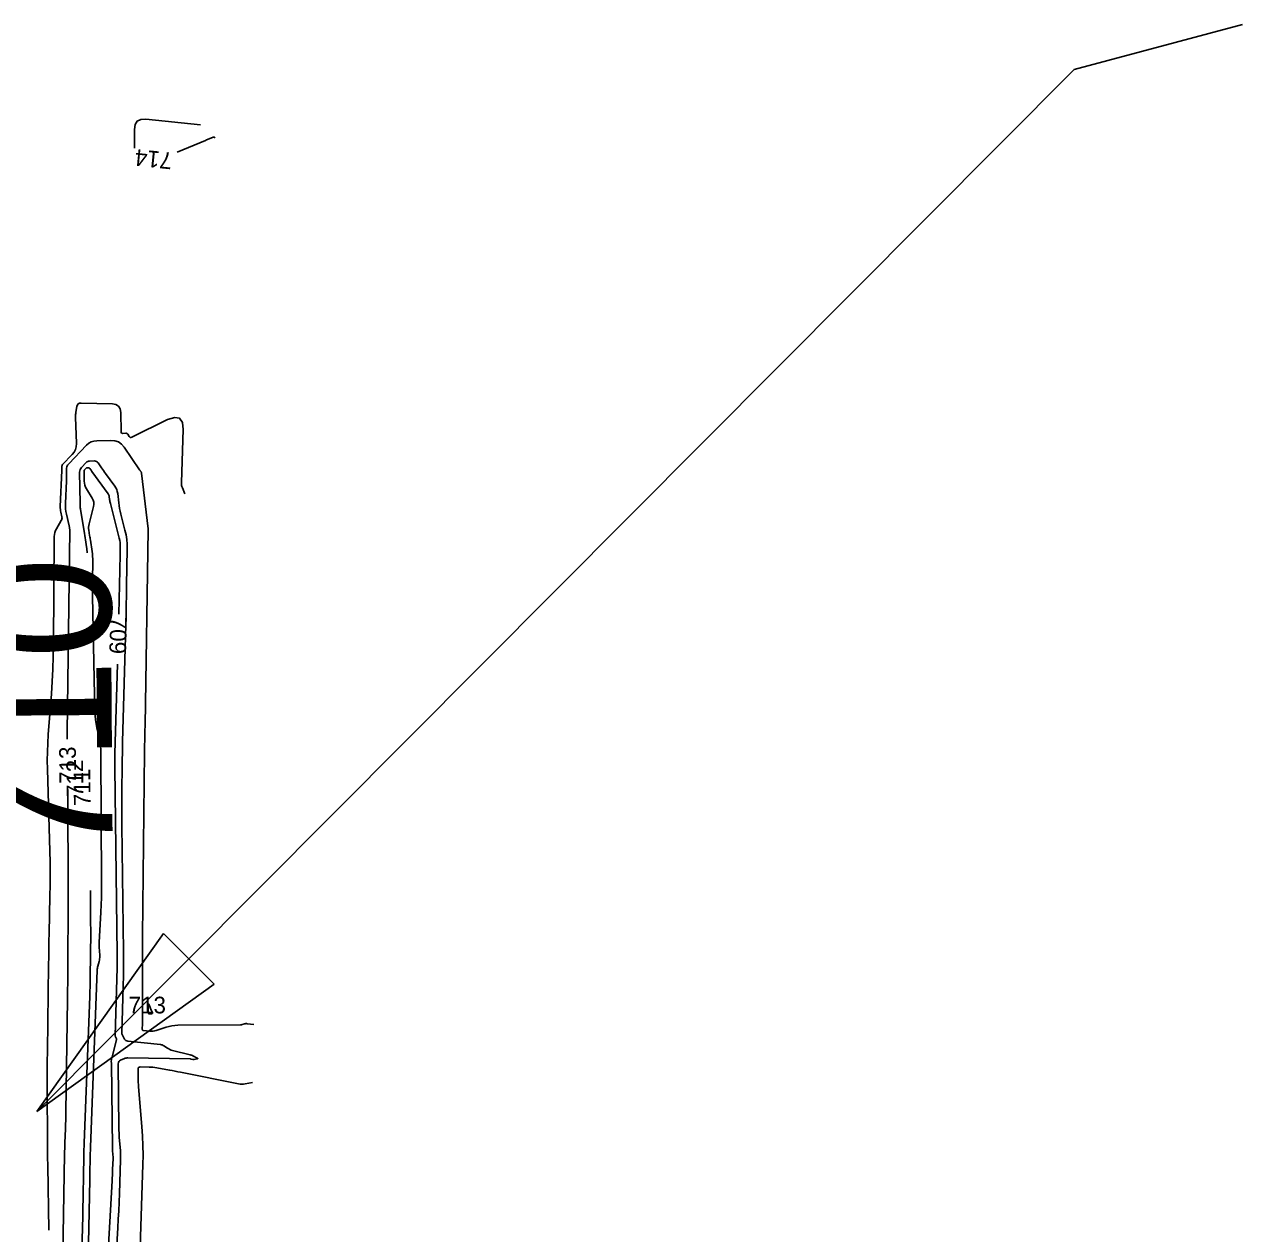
# Model space of a CAD drawing. Extents: x -361782338 to 28259792, y -263199453 to 8342113.
# Drawn here: x 1403882.9 to 1404174.4, y 578304.2 to 578593.6 of the extents above; entities that cross this region are included whole.
import ezdxf

# ---------------------------------------------------------------- set-up
doc = ezdxf.new("R2010")
doc.units = 0
for name, color, linetype in [('DT_X_Contour_Minor', 7, 'Continuous'), ('Level 19', 7, 'Continuous'), ('Level 40', 7, 'Continuous')]:
    doc.layers.add(name, color=color, linetype=linetype)

msp = doc.modelspace()

# ---------------------------------------------------------------- linework, layer by layer
at = {"layer": 'DT_X_Contour_Minor'}
for points in [[(1403925.03, 578569.52), (1403911.93, 578570.88), (1403910.74, 578570.83), (1403909.88, 578570.4), (1403909.37, 578569.6), (1403909.2, 578568.41), (1403909.21, 578563.97)], [(1403919.42, 578562.96), (1403926.19, 578565.8), (1403926.42, 578565.9), (1403926.65, 578565.99), (1403926.88, 578566.09), (1403927.1, 578566.19), (1403928.04, 578566.58), (1403928.11, 578566.6), (1403928.17, 578566.61), (1403928.22, 578566.6), (1403928.28, 578566.57), (1403928.55, 578566.42)], [(1403921.28, 578481.19), (1403920.68, 578482.62), (1403920.57, 578482.93), (1403920.49, 578483.24), (1403920.45, 578483.57), (1403920.44, 578483.89), (1403920.86, 578496.57), (1403920.68, 578498.32), (1403920, 578499.31), (1403918.83, 578499.52), (1403917.15, 578498.97), (1403908.55, 578494.77), (1403908.37, 578494.71), (1403908.21, 578494.72), (1403908.07, 578494.79), (1403907.95, 578494.93), (1403907.58, 578495.48), (1403907.49, 578495.59), (1403907.38, 578495.66), (1403907.26, 578495.7), (1403907.13, 578495.71), (1403906.34, 578495.69), (1403906.19, 578495.71), (1403906.09, 578495.77), (1403906.02, 578495.87), (1403906, 578496.02), (1403905.93, 578500.67), (1403905.79, 578501.55), (1403905.41, 578502.18), (1403904.78, 578502.57), (1403903.91, 578502.72), (1403896.42, 578502.94), (1403896.04, 578502.89), (1403895.74, 578502.74), (1403895.54, 578502.49), (1403895.42, 578502.12), (1403895.18, 578500.75), (1403895.14, 578500.46), (1403895.11, 578500.16), (1403895.1, 578499.87), (1403895.1, 578499.57), (1403895.32, 578493.25), (1403895.28, 578492.5), (1403895.09, 578491.81), (1403894.77, 578491.18), (1403894.31, 578490.59), (1403892.02, 578488.21), (1403891.94, 578488.1), (1403891.87, 578487.98), (1403891.84, 578487.85), (1403891.83, 578487.7), (1403891.84, 578487.23), (1403891.84, 578487.12), (1403891.84, 578487.02), (1403891.84, 578486.92), (1403891.83, 578486.82), (1403891.46, 578478.17), (1403891.46, 578477.83), (1403891.48, 578477.49), (1403891.52, 578477.15), (1403891.59, 578476.81), (1403891.84, 578475.72), (1403891.87, 578475.49), (1403891.86, 578475.27), (1403891.8, 578475.05), (1403891.7, 578474.84), (1403890.52, 578472.86), (1403890.29, 578472.43), (1403890.13, 578471.98), (1403890.04, 578471.52), (1403890, 578471.03), (1403889.83, 578445.24), (1403889.78, 578442.27), (1403889.68, 578439.29), (1403889.53, 578436.32), (1403889.33, 578433.35), (1403888.58, 578423.65), (1403888.44, 578421.58), (1403888.37, 578419.5), (1403888.34, 578417.41), (1403888.38, 578415.33), (1403888.95, 578395.73), (1403889.01, 578393.03), (1403889.03, 578390.32), (1403889.03, 578387.62), (1403888.98, 578384.92), (1403888.79, 578376.09), (1403888.75, 578374.19), (1403888.72, 578372.3), (1403888.68, 578370.41), (1403888.66, 578368.52), (1403888.36, 578347.94), (1403888.32, 578345.21), (1403888.3, 578342.48), (1403888.3, 578339.75), (1403888.31, 578337.01), (1403888.36, 578328.09), (1403888.37, 578326.17), (1403888.39, 578324.26), (1403888.42, 578322.35), (1403888.44, 578320.44)], [(1403937.79, 578354.22), (1403936.15, 578354.41), (1403935.99, 578354.43), (1403935.83, 578354.42), (1403935.67, 578354.4), (1403935.51, 578354.35), (1403935, 578354.19), (1403934.89, 578354.16), (1403934.78, 578354.14), (1403934.67, 578354.12), (1403934.55, 578354.12), (1403919.58, 578354.02), (1403918.88, 578353.99), (1403918.18, 578353.9), (1403917.49, 578353.77), (1403916.81, 578353.58), (1403914.37, 578352.79), (1403914.01, 578352.69), (1403913.65, 578352.63), (1403913.29, 578352.62), (1403912.92, 578352.63), (1403911.27, 578352.8), (1403911.23, 578352.81), (1403911.2, 578352.83), (1403911.17, 578352.85), (1403911.15, 578352.88), (1403911.09, 578352.99), (1403911.08, 578353.01), (1403911.07, 578353.04), (1403911.07, 578353.06), (1403911.06, 578353.09), (1403911.1, 578354.4), (1403911.11, 578354.68), (1403911.11, 578354.96), (1403911.11, 578355.24), (1403911.12, 578355.53), (1403911.15, 578368.69), (1403911.15, 578369.36), (1403911.15, 578370.02), (1403911.15, 578370.69), (1403911.14, 578371.35), (1403911.11, 578373.53), (1403911.11, 578373.99), (1403911.11, 578374.46), (1403911.11, 578374.93), (1403911.11, 578375.39), (1403911.6, 578419.37), (1403911.61, 578420.01), (1403911.62, 578420.65), (1403911.63, 578421.29), (1403911.65, 578421.93), (1403911.7, 578424.02), (1403911.71, 578424.47), (1403911.72, 578424.92), (1403911.73, 578425.37), (1403911.74, 578425.82), (1403912.51, 578472.56), (1403912.51, 578472.58), (1403912.51, 578472.61), (1403912.51, 578472.63), (1403912.5, 578472.66), (1403912.48, 578472.74), (1403912.48, 578472.76), (1403912.47, 578472.77), (1403912.47, 578472.79), (1403912.47, 578472.81), (1403910.91, 578486.13), (1403910.89, 578486.23), (1403910.86, 578486.32), (1403910.82, 578486.41), (1403910.77, 578486.49), (1403910.58, 578486.75), (1403910.54, 578486.8), (1403910.5, 578486.86), (1403910.46, 578486.91), (1403910.42, 578486.97), (1403906.77, 578492.36), (1403906.13, 578493.1), (1403905.39, 578493.63), (1403904.52, 578493.93), (1403903.55, 578494.01), (1403900.18, 578493.92), (1403899.49, 578493.84), (1403898.85, 578493.63), (1403898.27, 578493.3), (1403897.74, 578492.84), (1403893.47, 578488.38), (1403893.21, 578488.05), (1403893.03, 578487.7), (1403892.93, 578487.32), (1403892.9, 578486.92), (1403892.93, 578485.53), (1403892.93, 578485.23), (1403892.93, 578484.94), (1403892.92, 578484.64), (1403892.91, 578484.34), (1403892.68, 578478.91), (1403892.68, 578478.26), (1403892.71, 578477.61), (1403892.8, 578476.97), (1403892.92, 578476.33)], [(1403922.81, 578345.95), (1403923.19, 578345.87), (1403923.27, 578345.86), (1403923.35, 578345.86), (1403923.43, 578345.86), (1403923.51, 578345.87), (1403924.22, 578346), (1403924.33, 578346.03), (1403924.37, 578346.07), (1403924.35, 578346.13), (1403924.25, 578346.19), (1403923.34, 578346.66), (1403923.14, 578346.75), (1403922.94, 578346.84), (1403922.74, 578346.91), (1403922.53, 578346.97), (1403918.31, 578348.02), (1403918, 578348.11), (1403917.7, 578348.23), (1403917.41, 578348.37), (1403917.14, 578348.54), (1403916.25, 578349.12), (1403916.06, 578349.23), (1403915.85, 578349.32), (1403915.64, 578349.38), (1403915.42, 578349.41), (1403907.6, 578350.21), (1403907.36, 578350.27), (1403907.14, 578350.37), (1403906.96, 578350.52), (1403906.82, 578350.73), (1403906.39, 578351.48), (1403906.31, 578351.64), (1403906.25, 578351.81), (1403906.22, 578351.99), (1403906.22, 578352.17), (1403906.52, 578363.42), (1403906.54, 578364.23), (1403906.55, 578365.04), (1403906.56, 578365.85), (1403906.57, 578366.66), (1403906.58, 578369.31), (1403906.58, 578369.88), (1403906.57, 578370.44), (1403906.57, 578371.01), (1403906.56, 578371.58), (1403906.2, 578401.89), (1403906.18, 578403.88), (1403906.18, 578405.86), (1403906.18, 578407.85), (1403906.2, 578409.83), (1403906.27, 578416.32), (1403906.29, 578417.71), (1403906.31, 578419.1), (1403906.34, 578420.49), (1403906.37, 578421.88), (1403907.12, 578449.87), (1403907.18, 578452.23), (1403907.23, 578454.58), (1403907.28, 578456.94), (1403907.32, 578459.3), (1403907.46, 578468.03), (1403907.45, 578469.17), (1403907.35, 578470.3), (1403907.18, 578471.42), (1403906.94, 578472.53), (1403905.96, 578476.36), (1403905.8, 578477.04), (1403905.66, 578477.71), (1403905.54, 578478.4), (1403905.45, 578479.08), (1403905.19, 578481.33), (1403905.1, 578481.8), (1403904.96, 578482.25), (1403904.76, 578482.67), (1403904.5, 578483.07), (1403902.29, 578486.08), (1403902.04, 578486.43), (1403901.79, 578486.77), (1403901.55, 578487.12), (1403901.31, 578487.47), (1403900.53, 578488.62), (1403900.35, 578488.83), (1403900.14, 578488.98), (1403899.89, 578489.07), (1403899.61, 578489.1), (1403898.46, 578489.06), (1403898.22, 578489.04), (1403898.01, 578488.96), (1403897.81, 578488.85), (1403897.63, 578488.69), (1403896.53, 578487.55), (1403896.33, 578487.3), (1403896.19, 578487.02), (1403896.1, 578486.71), (1403896.08, 578486.38), (1403896.23, 578478.9), (1403896.23, 578478.79), (1403896.23, 578478.68), (1403896.23, 578478.58), (1403896.22, 578478.47)], [(1403905.43, 578452.44), (1403905.71, 578462.95), (1403905.73, 578463.71), (1403905.74, 578464.47), (1403905.76, 578465.23), (1403905.77, 578466), (1403905.81, 578468.48), (1403905.8, 578469.02), (1403905.76, 578469.54), (1403905.68, 578470.07), (1403905.57, 578470.58), (1403903.45, 578478.88), (1403903.39, 578479.12), (1403903.34, 578479.35), (1403903.3, 578479.59), (1403903.27, 578479.83), (1403903.18, 578480.61), (1403903.15, 578480.77), (1403903.1, 578480.93), (1403903.03, 578481.08), (1403902.94, 578481.22), (1403899.04, 578486.53), (1403898.96, 578486.63), (1403898.89, 578486.74), (1403898.81, 578486.85), (1403898.74, 578486.95), (1403898.5, 578487.31), (1403898.44, 578487.37), (1403898.38, 578487.42), (1403898.3, 578487.45), (1403898.22, 578487.45), (1403897.86, 578487.44), (1403897.79, 578487.44), (1403897.72, 578487.41), (1403897.66, 578487.38), (1403897.61, 578487.33), (1403897.27, 578486.98), (1403897.21, 578486.9), (1403897.16, 578486.81), (1403897.14, 578486.72), (1403897.13, 578486.62), (1403897.18, 578484.27), (1403897.22, 578483.77), (1403897.32, 578483.3), (1403897.49, 578482.84), (1403897.73, 578482.4), (1403899.09, 578480.19), (1403899.32, 578479.71), (1403899.45, 578479.21), (1403899.48, 578478.7), (1403899.39, 578478.17), (1403898.33, 578474.03), (1403898.26, 578473.65), (1403898.22, 578473.26), (1403898.22, 578472.88), (1403898.27, 578472.49), (1403898.48, 578471.23), (1403898.52, 578470.95), (1403898.57, 578470.68), (1403898.61, 578470.41), (1403898.65, 578470.14), (1403899.07, 578467.41), (1403899.14, 578466.82), (1403899.2, 578466.24), (1403899.23, 578465.65), (1403899.23, 578465.06), (1403899.17, 578460.57), (1403899.16, 578459.61), (1403899.16, 578458.65), (1403899.17, 578457.68), (1403899.19, 578456.72), (1403899.75, 578429.02), (1403899.79, 578428.05), (1403899.88, 578427.09), (1403900.02, 578426.14), (1403900.21, 578425.19), (1403900.89, 578422.1), (1403901.01, 578421.43), (1403901.11, 578420.76), (1403901.16, 578420.09), (1403901.19, 578419.41), (1403901.34, 578388.07), (1403901.33, 578386.32), (1403901.3, 578384.57), (1403901.25, 578382.82), (1403901.17, 578381.07), (1403900.79, 578373.81), (1403900.77, 578373.36), (1403900.76, 578372.91), (1403900.77, 578372.46), (1403900.8, 578372.01), (1403900.89, 578370.53), (1403900.89, 578370.22), (1403900.87, 578369.91), (1403900.83, 578369.6), (1403900.75, 578369.29), (1403900.44, 578368.18), (1403900.38, 578367.94), (1403900.33, 578367.69), (1403900.3, 578367.45), (1403900.29, 578367.2)], [(1403892.92, 578476.33), (1403893.57, 578473.53), (1403893.59, 578473.45), (1403893.6, 578473.37), (1403893.62, 578473.29), (1403893.63, 578473.21), (1403893.68, 578472.92), (1403893.69, 578472.88), (1403893.69, 578472.83), (1403893.7, 578472.79), (1403893.71, 578472.75), (1403893.73, 578472.61), (1403893.73, 578472.58), (1403893.73, 578472.54), (1403893.74, 578472.51), (1403893.74, 578472.48), (1403893.11, 578424.21), (1403893.11, 578423.74), (1403893.11, 578423.26), (1403893.11, 578422.78), (1403893.12, 578422.49)], [(1403896.22, 578478.47), (1403896.21, 578478.09), (1403896.21, 578478.03), (1403896.21, 578477.97), (1403896.22, 578477.9), (1403896.23, 578477.84), (1403896.28, 578477.64), (1403896.29, 578477.59), (1403896.3, 578477.55), (1403896.3, 578477.51), (1403896.31, 578477.46), (1403897.18, 578472.24), (1403897.26, 578471.73), (1403897.35, 578471.22), (1403897.43, 578470.71), (1403897.51, 578470.2), (1403897.76, 578468.53), (1403897.81, 578468.17), (1403897.84, 578467.81), (1403897.86, 578467.45), (1403897.86, 578467.09)], [(1403901.44, 578274.79), (1403903.86, 578316.79), (1403903.9, 578317.47), (1403903.93, 578318.14), (1403903.96, 578318.82), (1403903.98, 578319.5), (1403904.07, 578322.16), (1403904.07, 578322.41), (1403904.07, 578322.66), (1403904.06, 578322.91), (1403904.04, 578323.16), (1403903.97, 578323.97), (1403903.96, 578324.15), (1403903.95, 578324.32), (1403903.95, 578324.5), (1403903.94, 578324.67), (1403903.74, 578345.02), (1403903.73, 578345.05), (1403903.73, 578345.08), (1403903.71, 578345.1), (1403903.7, 578345.12), (1403903.64, 578345.19), (1403903.63, 578345.2), (1403903.62, 578345.22), (1403903.62, 578345.23), (1403903.62, 578345.25), (1403903.72, 578345.92), (1403903.74, 578346.06), (1403903.77, 578346.2), (1403903.8, 578346.34), (1403903.84, 578346.48), (1403904.9, 578350.51), (1403904.92, 578350.62), (1403904.92, 578350.72), (1403904.89, 578350.83), (1403904.85, 578350.93), (1403904.67, 578351.25), (1403904.63, 578351.32), (1403904.61, 578351.4), (1403904.59, 578351.47), (1403904.59, 578351.55), (1403905.03, 578367.74), (1403905.04, 578368.07), (1403905.04, 578368.4), (1403905.05, 578368.73), (1403905.05, 578369.05), (1403905.05, 578370.12), (1403905.05, 578370.35), (1403905.05, 578370.58), (1403905.05, 578370.81), (1403905.05, 578371.04), (1403904.51, 578415.65), (1403904.51, 578415.99), (1403904.51, 578416.33), (1403904.51, 578416.67), (1403904.51, 578417), (1403904.53, 578418.11), (1403904.53, 578418.34), (1403904.53, 578418.58), (1403904.54, 578418.82), (1403904.54, 578419.05), (1403905.11, 578440.44)], [(1403893.23, 578410.49), (1403893.3, 578385), (1403893.31, 578378.8), (1403893.29, 578372.6), (1403893.24, 578366.41), (1403893.17, 578360.21), (1403892.79, 578333.32), (1403892.77, 578332.3), (1403892.75, 578331.29), (1403892.72, 578330.27), (1403892.69, 578329.25), (1403892.56, 578325.93), (1403892.53, 578325.22), (1403892.51, 578324.51), (1403892.49, 578323.79), (1403892.48, 578323.08), (1403891.81, 578284.88)], [(1403898.66, 578386.3), (1403898.68, 578384.77), (1403898.7, 578383.23), (1403898.71, 578381.7), (1403898.71, 578380.17), (1403898.73, 578375.16), (1403898.73, 578374.08), (1403898.72, 578373.01), (1403898.71, 578371.94), (1403898.7, 578370.86), (1403898.63, 578365.52), (1403898.61, 578364.37), (1403898.58, 578363.23), (1403898.55, 578362.08), (1403898.51, 578360.94), (1403897.25, 578327.94), (1403897.18, 578325.78), (1403897.11, 578323.62), (1403897.06, 578321.46), (1403897.01, 578319.3), (1403896.89, 578312.25), (1403896.86, 578310.74), (1403896.83, 578309.23), (1403896.81, 578307.72), (1403896.78, 578306.21), (1403896.22, 578278.06)], [(1403900.29, 578367.2), (1403898.68, 578324.89), (1403898.65, 578324.11), (1403898.63, 578323.33), (1403898.61, 578322.55), (1403898.59, 578321.77), (1403898.55, 578319.22), (1403898.54, 578318.67), (1403898.53, 578318.13), (1403898.51, 578317.58), (1403898.5, 578317.03), (1403897.68, 578275.22), (1403897.67, 578274.75), (1403897.66, 578274.28), (1403897.65, 578273.81), (1403897.64, 578273.35), (1403897.6, 578271.81), (1403897.6, 578271.49), (1403897.59, 578271.16), (1403897.59, 578270.83), (1403897.59, 578270.5)], [(1403912.5, 578358.87), (1403912.52, 578357.05), (1403912.54, 578356.92), (1403912.6, 578356.82), (1403912.7, 578356.77), (1403912.84, 578356.76), (1403913.35, 578356.8), (1403913.44, 578356.83), (1403913.5, 578356.87), (1403913.51, 578356.94), (1403913.49, 578357.03), (1403913.36, 578357.37), (1403913.33, 578357.45), (1403913.3, 578357.52), (1403913.27, 578357.6), (1403913.24, 578357.67), (1403912.72, 578358.92), (1403912.62, 578359.12), (1403912.55, 578359.18), (1403912.51, 578359.1), (1403912.5, 578358.87)], [(1403903.58, 578277.08), (1403905.23, 578305.54), (1403905.34, 578307.59), (1403905.44, 578309.64), (1403905.52, 578311.69), (1403905.6, 578313.74), (1403905.86, 578321.79), (1403905.87, 578322.55), (1403905.86, 578323.3), (1403905.83, 578324.06), (1403905.78, 578324.81), (1403905.57, 578327.27), (1403905.53, 578327.8), (1403905.51, 578328.33), (1403905.49, 578328.86), (1403905.48, 578329.39), (1403905.32, 578344.84), (1403905.35, 578345.12), (1403905.46, 578345.36), (1403905.63, 578345.54), (1403905.88, 578345.68), (1403906.81, 578346.06), (1403907.01, 578346.13), (1403907.21, 578346.18), (1403907.42, 578346.21), (1403907.63, 578346.22), (1403922.52, 578345.99), (1403922.55, 578345.99), (1403922.58, 578345.99), (1403922.61, 578345.99), (1403922.64, 578345.98), (1403922.73, 578345.96), (1403922.75, 578345.96), (1403922.77, 578345.96), (1403922.79, 578345.95), (1403922.81, 578345.95)], [(1403910.1, 578286.04), (1403911.22, 578320.68), (1403911.26, 578322.96), (1403911.24, 578325.23), (1403911.15, 578327.5), (1403910.99, 578329.77), (1403910.2, 578339.29), (1403910.16, 578339.82), (1403910.13, 578340.35), (1403910.11, 578340.88), (1403910.1, 578341.41), (1403910.07, 578343.77), (1403910.08, 578343.83), (1403910.1, 578343.88), (1403910.14, 578343.92), (1403910.19, 578343.94), (1403910.38, 578344.02), (1403910.42, 578344.04), (1403910.46, 578344.05), (1403910.51, 578344.05), (1403910.55, 578344.05), (1403912.72, 578344.02), (1403913.18, 578344), (1403913.64, 578343.97), (1403914.1, 578343.91), (1403914.56, 578343.84), (1403917.6, 578343.29), (1403918.26, 578343.17), (1403918.91, 578343.04), (1403919.56, 578342.92), (1403920.21, 578342.79), (1403934.14, 578340), (1403934.53, 578339.94), (1403934.91, 578339.92), (1403935.3, 578339.93), (1403935.69, 578339.99), (1403937.49, 578340.3)], [(1403888.44, 578320.44), (1403888.69, 578305.01)]]:
    msp.add_lwpolyline(points, dxfattribs=at)
at = {"layer": 'Level 40'}
for p, q in [((1403885.81, 578333.4), (1403916.13, 578376)), ((1403916.13, 578376), (1403928.3, 578363.88)), ((1403928.3, 578363.88), (1403885.81, 578333.4))]:
    msp.add_line(p, q, dxfattribs=at)
msp.add_lwpolyline([(1403885.81, 578333.4), (1404134.11, 578582.76), (1404174.43, 578593.56)], dxfattribs=at)

# ---------------------------------------------------------------- texts
at = {"layer": 'Level 19'}
for s, height, rotation, p in [('714', 4, 174.3217, (1403918.4, 578562.84)), ('710', 33, 90.3957, (1403904.01, 578392.66)), ('709', 4, 268.4817, (1403903.41, 578451.86)), ('713', 4, 90.5649, (1403895.26, 578411.84)), ('712', 4, 90.7332, (1403897, 578408.68)), ('711', 4, 90.7375, (1403898.72, 578406.51))]:
    msp.add_text(s, height=height, rotation=rotation, dxfattribs=at).set_placement(p)
msp.add_text('713', height=4, dxfattribs=at).set_placement((1403907.82, 578356.87))

doc.saveas('drawing.dxf')
